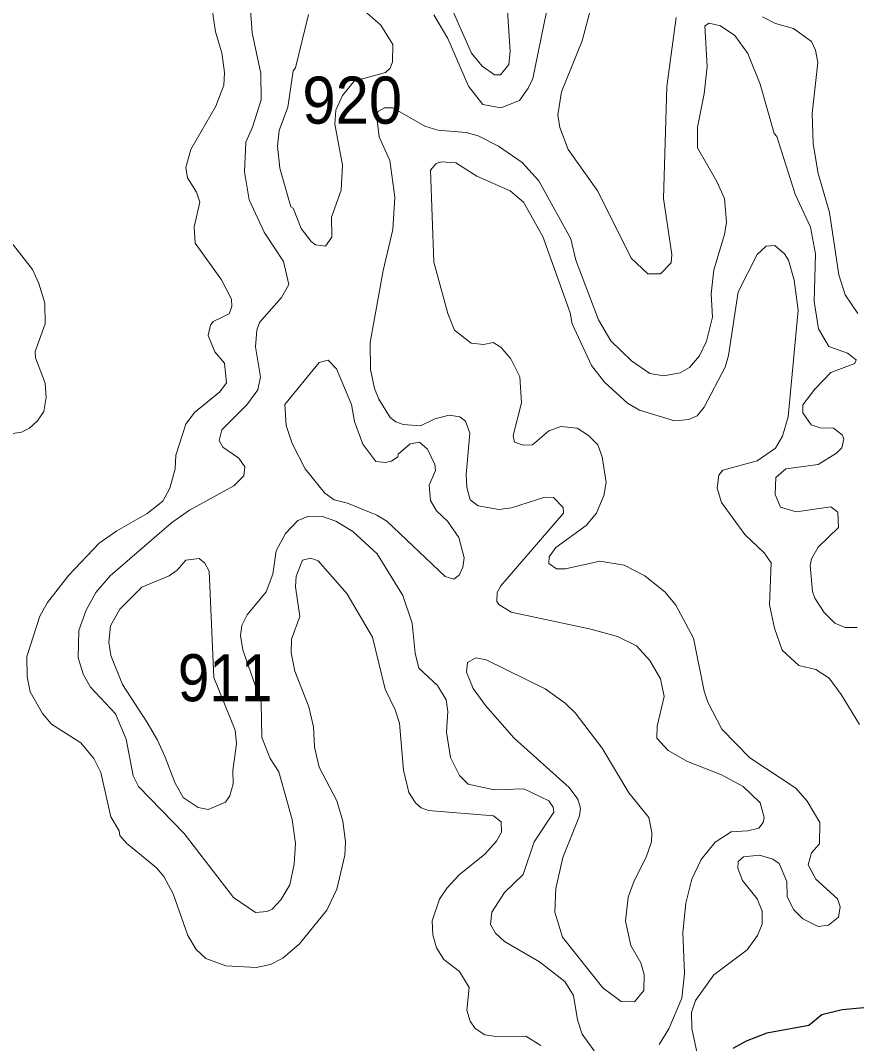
# Model space of a CAD drawing. Extents: x 763.2 to 816.8, y 7896.5 to 7952.7.
# Drawn here: x 767.387 to 770.229, y 7935.931 to 7939.409 of the extents above; entities that cross this region are included whole.
import ezdxf

# ---------------------------------------------------------------- set-up
doc = ezdxf.new("R2010")
doc.units = 0
doc.header["$LTSCALE"] = 0.064
doc.layers.add('1', color=7, linetype='Continuous', lineweight=25)
doc.layers.add('2', color=7, linetype='Continuous', lineweight=13)
doc.layers.add('21', color=7, linetype='Continuous')

msp = doc.modelspace()

# ---------------------------------------------------------------- linework, layer by layer
at = {"layer": '1'}
msp.add_lwpolyline([(770.2539, 7936.0529), (770.1802, 7936.0457), (770.1103, 7936.0282), (770.0661, 7935.9925), (769.9238, 7935.9668), (769.853, 7935.9394), (769.8084, 7935.9144)], dxfattribs=at)
at = {"layer": '2'}
for points in [[(768.8191, 7939.527), (768.9205, 7939.2984), (768.9566, 7939.254), (768.9981, 7939.2244), (769.0189, 7939.2247), (769.0465, 7939.2592), (769.0518, 7939.3042), (769.0421, 7939.4422)], [(767.551, 7937.5229), (767.655, 7937.6317), (767.7146, 7937.6738), (767.8181, 7937.7329), (767.8707, 7937.7754), (767.8943, 7937.8196), (767.9128, 7937.8844), (767.9149, 7937.9317), (767.9496, 7938.0367), (767.9782, 7938.0767), (768.0647, 7938.1468), (768.0873, 7938.1773), (768.0806, 7938.2443), (768.0482, 7938.2822), (768.025, 7938.3384), (768.0325, 7938.3732), (768.0416, 7938.3861), (768.0961, 7938.4122), (768.105, 7938.4373), (768.1048, 7938.4622), (768.07, 7938.5279), (767.9805, 7938.6517), (767.9771, 7938.7076), (767.9966, 7938.7915), (767.9854, 7938.8259), (767.9547, 7938.8737), (767.9492, 7938.9098), (767.9662, 7938.971), (768.051, 7939.1176), (768.0777, 7939.1891), (768.0806, 7939.2326), (768.0711, 7939.2991), (768.0497, 7939.37), (768.0363, 7939.4627)], [(768.1122, 7937.8272), (768.1462, 7937.8611), (768.1493, 7937.8914), (768.1288, 7937.9216), (768.0746, 7937.9585), (768.0627, 7937.9808), (768.0717, 7938.0175), (768.1562, 7938.1019), (768.1937, 7938.1539), (768.2023, 7938.198), (768.1859, 7938.2998), (768.1901, 7938.356), (768.1994, 7938.3829), (768.2745, 7938.4671), (768.2991, 7938.511), (768.2813, 7938.5895), (768.2158, 7938.6897), (768.1649, 7938.7992), (768.1485, 7938.8943), (768.1525, 7938.9959), (768.1761, 7939.0459), (768.2055, 7939.1388), (768.2039, 7939.2286), (768.1745, 7939.3666), (768.1678, 7939.4601)], [(769.3262, 7939.4555), (769.2965, 7939.3404), (769.226, 7939.1662), (769.2131, 7939.0886), (769.2206, 7939.0451), (769.2488, 7938.9703), (769.3491, 7938.8283), (769.4629, 7938.6007), (769.5195, 7938.5479), (769.5629, 7938.5475), (769.5986, 7938.585), (769.6007, 7938.6133), (769.5729, 7938.8039), (769.5841, 7939.1843), (769.6155, 7939.4193)], [(768.3664, 7939.4292), (768.3219, 7939.2487), (768.3143, 7939.2374), (768.296, 7939.1143), (768.2664, 7939.0355), (768.2609, 7938.982), (768.2685, 7938.9073), (768.3059, 7938.7756), (768.3137, 7938.7705), (768.3415, 7938.7015), (768.375, 7938.6575), (768.3901, 7938.6469), (768.4238, 7938.6415), (768.4448, 7938.6725), (768.4441, 7938.7409), (768.4768, 7938.8323), (768.4816, 7938.9176), (768.4552, 7939.0566), (768.4589, 7939.1042), (768.4817, 7939.1537), (768.5212, 7939.2028), (768.6281, 7939.2321), (768.6434, 7939.2466), (768.651, 7939.2686), (768.6526, 7939.3272), (768.6114, 7939.3936), (768.5572, 7939.4413)], [(768.7922, 7939.4282), (768.8399, 7939.3476), (768.9093, 7939.186), (768.9587, 7939.1236), (769.0199, 7939.1127), (769.083, 7939.1375), (769.113, 7939.179), (769.1284, 7939.212), (769.1747, 7939.4382)], [(769.9092, 7939.422), (769.9535, 7939.3989), (770.0139, 7939.3817), (770.0752, 7939.3377), (770.0891, 7939.3086), (770.097, 7939.2668), (770.0775, 7939.0927), (770.081, 7938.9903), (770.0983, 7938.8891), (770.1363, 7938.7567), (770.169, 7938.5446), (770.1895, 7938.476), (770.2331, 7938.413)], [(770.1647, 7937.7375), (770.1415, 7937.7551), (770.0239, 7937.7388), (769.9705, 7937.7543), (769.9524, 7937.7977), (769.9547, 7937.8557), (769.9884, 7937.8845), (770.0987, 7937.9), (770.1604, 7937.9379), (770.1782, 7937.9562), (770.1859, 7937.9868), (770.1803, 7938.0006), (770.1503, 7938.0228), (770.1045, 7938.0244), (770.0745, 7938.034), (770.0464, 7938.0757), (770.0462, 7938.1024), (770.0867, 7938.1557), (770.141, 7938.2118), (770.2232, 7938.2429), (770.2269, 7938.2552), (770.1981, 7938.2782), (770.1347, 7938.3013), (770.0991, 7938.3609), (770.0841, 7938.4536), (770.0888, 7938.6153), (770.0726, 7938.706), (770.0197, 7938.8191), (769.9575, 7939.0149), (769.9491, 7939.0251), (769.9007, 7939.1923), (769.8588, 7939.2973), (769.8148, 7939.3583), (769.7662, 7939.3905), (769.7281, 7939.4), (769.7133, 7939.3907), (769.7207, 7939.253), (769.7108, 7939.1596), (769.688, 7939.0459), (769.6885, 7938.9757), (769.7533, 7938.8618), (769.7794, 7938.8034), (769.7865, 7938.7231), (769.78, 7938.6811), (769.7437, 7938.5613), (769.734, 7938.4799), (769.7388, 7938.4005), (769.7191, 7938.3188), (769.695, 7938.2695), (769.6604, 7938.229), (769.6297, 7938.2114), (769.5736, 7938.2006), (769.5264, 7938.2092), (769.4639, 7938.2519), (769.3933, 7938.3195), (769.3511, 7938.3912), (769.275, 7938.5945), (769.2575, 7938.6665), (769.1489, 7938.8644), (769.0919, 7938.9264), (769.0118, 7938.9815), (768.9424, 7939.017), (768.9023, 7939.0287), (768.806, 7939.0366), (768.7609, 7939.0496), (768.6522, 7939.1124), (768.6241, 7939.1122), (768.6036, 7939.1008), (768.5967, 7939.0884), (768.6064, 7939.0133), (768.6426, 7938.9328), (768.6592, 7938.8083), (768.6528, 7938.6982), (768.6199, 7938.5595), (768.5754, 7938.3148), (768.5772, 7938.2229), (768.5903, 7938.1579), (768.6051, 7938.1217), (768.6439, 7938.0599), (768.6626, 7938.0444), (768.6872, 7938.0351), (768.7462, 7938.0315), (768.7959, 7938.0553), (768.844, 7938.0672), (768.8805, 7938.0615), (768.8992, 7938.0471), (768.9138, 7938.0059), (768.9024, 7937.8659), (768.9043, 7937.8211), (768.9159, 7937.7796), (768.9432, 7937.7593), (769.0132, 7937.7471), (769.0559, 7937.7525), (769.1694, 7937.788), (769.1992, 7937.7879)], [(769.9328, 7937.4222), (769.9389, 7937.5648), (769.9146, 7937.5989), (769.849, 7937.6615), (769.7699, 7937.7706), (769.7555, 7937.8186), (769.7604, 7937.8628), (769.7744, 7937.8801), (769.8904, 7937.9124), (769.9531, 7937.9546), (769.9768, 7937.9961), (769.9963, 7938.0611), (770.0297, 7938.424), (770.0166, 7938.5259), (769.997, 7938.5943), (769.9838, 7938.6158), (769.9506, 7938.644), (769.9216, 7938.6423), (769.8905, 7938.6135), (769.826, 7938.4865), (769.7929, 7938.2696), (769.7817, 7938.2308), (769.7107, 7938.0941), (769.6866, 7938.0648), (769.6583, 7938.0527), (769.6097, 7938.0477), (769.4908, 7938.084), (769.4501, 7938.1086), (769.3718, 7938.1797), (769.3274, 7938.2366), (769.2625, 7938.3774), (769.2554, 7938.4147), (769.1629, 7938.675), (769.0972, 7938.791), (769.0511, 7938.8302), (768.938, 7938.8796), (768.867, 7938.9252), (768.8176, 7938.9285), (768.8003, 7938.9233), (768.781, 7938.9006), (768.7924, 7938.5879), (768.8395, 7938.4133), (768.8624, 7938.3563), (768.9184, 7938.3121), (768.9604, 7938.3073), (768.9932, 7938.3139), (769.0194, 7938.2982), (769.0538, 7938.2591), (769.0843, 7938.1974), (769.0897, 7938.1094), (769.0621, 7937.9982), (769.0666, 7937.976), (769.0956, 7937.9658), (769.1278, 7937.967), (769.1831, 7938.0138), (769.2238, 7938.0293), (769.2786, 7938.0229), (769.3171, 7937.9978), (769.3494, 7937.9663), (769.3641, 7937.9256), (769.3772, 7937.8382), (769.3693, 7937.7939), (769.3443, 7937.7339), (769.3095, 7937.6926), (769.2071, 7937.6175), (769.1835, 7937.5858), (769.1823, 7937.5627), (769.2084, 7937.5447), (769.239, 7937.5451), (769.356, 7937.571), (769.4389, 7937.5568), (769.5091, 7937.521), (769.5777, 7937.4659), (769.6147, 7937.4217), (769.6746, 7937.3097), (769.7103, 7937.1289), (769.7231, 7937.0915), (769.7705, 7937.0003), (769.866, 7936.9019), (770.0221, 7936.7997), (770.0604, 7936.7549), (770.1039, 7936.6821), (770.1025, 7936.6102), (770.0759, 7936.5799), (770.0647, 7936.5388), (770.0904, 7936.4901), (770.1636, 7936.4231), (770.1725, 7936.3959), (770.1678, 7936.3606), (770.1337, 7936.3329), (770.0984, 7936.3287), (770.0457, 7936.3554), (770.0144, 7936.3869), (769.9923, 7936.4308), (769.9917, 7936.4822)], [(767.3266, 7938.913), (767.2924, 7938.8208), (767.292, 7938.7792), (767.3036, 7938.7324), (767.3188, 7938.7022), (767.4281, 7938.562)], [(767.4281, 7938.562), (767.4498, 7938.5154), (767.4704, 7938.4485), (767.4707, 7938.3774), (767.4366, 7938.2835), (767.4383, 7938.2623), (767.4707, 7938.1763), (767.4741, 7938.1268), (767.4663, 7938.08), (767.4454, 7938.0485), (767.4172, 7938.0235), (767.3902, 7938.0092), (767.3517, 7938.0035)], [(767.61, 7937.4038), (767.6436, 7937.4642), (767.6923, 7937.5212), (767.8999, 7937.7008), (767.9618, 7937.7448), (768.1122, 7937.8272)], [(769.1992, 7937.7879), (769.2317, 7937.7532), (769.2325, 7937.7337), (769.0201, 7937.4868), (769.0073, 7937.4647), (769.0064, 7937.4337)], [(769.3369, 7935.9058), (769.2966, 7935.9628), (769.2803, 7936.0121), (769.2668, 7936.0942), (769.2369, 7936.1418), (769.1515, 7936.209), (769.0321, 7936.2777), (769.0019, 7936.3061), (768.9848, 7936.336), (768.9889, 7936.3776), (769.0316, 7936.4447), (769.0953, 7936.5059), (769.1327, 7936.6168), (769.1994, 7936.7175), (769.1979, 7936.7343), (769.1832, 7936.7556), (769.0976, 7936.7965), (768.9971, 7936.7938), (768.9084, 7936.8131), (768.879, 7936.842), (768.8484, 7936.903), (768.8349, 7936.9898), (768.8398, 7937.0599), (768.8335, 7937.0999), (768.8041, 7937.1481), (768.7413, 7937.2071), (768.7285, 7937.2581), (768.7179, 7937.3598), (768.6863, 7937.4539), (768.5999, 7937.5957), (768.5171, 7937.6717), (768.4588, 7937.7065), (768.4138, 7937.7227), (768.3667, 7937.7238), (768.3296, 7937.7089), (768.2877, 7937.6647), (768.2565, 7937.6056), (768.2446, 7937.5263), (768.2222, 7937.4667), (768.1579, 7937.3886), (768.1397, 7937.3519), (768.135, 7937.3183), (768.1425, 7937.269), (768.2053, 7937.0903), (768.2072, 7936.9713), (768.2362, 7936.8998), (768.2647, 7936.8552), (768.3104, 7936.6924), (768.3221, 7936.611), (768.3172, 7936.5413), (768.3021, 7936.471), (768.2722, 7936.4197), (768.2422, 7936.3883), (768.2252, 7936.3796), (768.1853, 7936.3767), (768.1114, 7936.4278), (767.943, 7936.6453), (767.7884, 7936.8044), (767.7696, 7936.8412), (767.746, 7936.9653), (767.71, 7937.0514), (767.6254, 7937.1422), (767.6011, 7937.1842), (767.583, 7937.2426), (767.5859, 7937.3354), (767.61, 7937.4038)], [(770.0789, 7937.4682), (770.071, 7937.5564), (770.076, 7937.5791), (770.098, 7937.6181), (770.1676, 7937.6857), (770.1647, 7937.7375)], [(769.1554, 7935.9243), (769.1045, 7935.9556), (769.0109, 7935.954), (768.9651, 7935.9607), (768.9322, 7935.9823), (768.9158, 7936.0068), (768.904, 7936.045), (768.9124, 7936.122), (768.8791, 7936.176), (768.826, 7936.2163), (768.8006, 7936.2565), (768.7891, 7936.3001), (768.7864, 7936.3483), (768.8117, 7936.4217), (768.8373, 7936.4605), (768.8777, 7936.5045), (768.9648, 7936.5752), (769.0053, 7936.619), (769.0221, 7936.6492), (769.0206, 7936.6845), (768.9945, 7936.705), (768.7741, 7936.7231), (768.7488, 7936.7327), (768.7293, 7936.7498), (768.7069, 7936.7846), (768.6885, 7936.8609), (768.6757, 7937.0198), (768.661, 7937.0659), (768.6267, 7937.136), (768.5834, 7937.313), (768.4963, 7937.4609), (768.3992, 7937.5716), (768.3737, 7937.581), (768.3458, 7937.5744), (768.3238, 7937.5203), (768.3223, 7937.4842), (768.337, 7937.3833), (768.3081, 7937.3056), (768.3075, 7937.2588), (768.3192, 7937.1974), (768.3667, 7937.0757), (768.3828, 7937.0081), (768.3864, 7936.939), (768.4024, 7936.8708), (768.4628, 7936.7557), (768.4828, 7936.6867), (768.4914, 7936.6162), (768.4899, 7936.5717), (768.4621, 7936.4559), (768.4281, 7936.3848), (768.3358, 7936.2701), (768.2783, 7936.2207), (768.2365, 7936.1996), (768.1884, 7936.189), (768.0846, 7936.1955), (768.0172, 7936.2206), (767.9842, 7936.2509), (767.9555, 7936.2981), (767.9062, 7936.4394), (767.8748, 7936.4985), (767.849, 7936.5287), (767.7475, 7936.6126), (767.7247, 7936.6387), (767.722, 7936.6537), (767.6942, 7936.7014), (767.6601, 7936.8523), (767.6361, 7936.9003), (767.5924, 7936.9531), (767.493, 7937.0167), (767.4618, 7937.0531), (767.4196, 7937.1272)], [(767.4196, 7937.1272), (767.4093, 7937.1772), (767.4085, 7937.2473), (767.4524, 7937.384), (767.4788, 7937.4308), (767.551, 7937.5229)], [(770.2307, 7937.345), (770.1905, 7937.3458), (770.1545, 7937.3598), (770.119, 7937.3964), (770.0873, 7937.4446), (770.0789, 7937.4682)], [(769.0064, 7937.4337), (769.0124, 7937.4238), (769.0543, 7937.397), (769.3256, 7937.3395), (769.4157, 7937.3143)], [(770.1354, 7937.1727), (770.0903, 7937.2029), (770.0328, 7937.2165), (769.9754, 7937.2678), (769.9494, 7937.3427), (769.9328, 7937.4222)], [(769.4157, 7937.3143), (769.4807, 7937.2834), (769.5262, 7937.2328), (769.5619, 7937.1704), (769.5744, 7937.1111), (769.5515, 7937.01), (769.5498, 7936.9696), (769.5882, 7936.9272), (769.6545, 7936.8894), (769.7695, 7936.8449), (769.843, 7936.8048), (769.9007, 7936.7489), (769.9146, 7936.6991), (769.9112, 7936.6822), (769.8967, 7936.6634), (769.8588, 7936.6541), (769.8029, 7936.6505), (769.7484, 7936.6153), (769.701, 7936.557), (769.6694, 7936.49), (769.6485, 7936.4085), (769.6387, 7936.3088), (769.6435, 7936.1692), (769.6348, 7936.0857), (769.5905, 7935.9813), (769.5573, 7935.9272)], [(770.2385, 7937.0152), (770.1768, 7937.1171), (770.1354, 7937.1727)], [(769.9917, 7936.4822), (769.9659, 7936.5431), (769.9445, 7936.5576), (769.8983, 7936.5717), (769.8442, 7936.5655), (769.8261, 7936.5495)], [(769.8261, 7936.5495), (769.8247, 7936.5271), (769.8406, 7936.4855), (769.8912, 7936.4229), (769.9083, 7936.3805), (769.9081, 7936.3368), (769.8919, 7936.2979), (769.857, 7936.2498), (769.7439, 7936.1642), (769.6814, 7936.0772), (769.6682, 7936.037), (769.669, 7935.9822), (769.7056, 7935.8124)]]:
    msp.add_lwpolyline(points, dxfattribs=at)
for points in [[(768.6317, 7937.7066), (768.5986, 7937.7278), (768.4987, 7937.768), (768.4535, 7937.7794), (768.4214, 7937.8021), (768.3545, 7937.8849), (768.3108, 7937.9705), (768.2905, 7938.0319), (768.2859, 7938.1032), (768.4021, 7938.2459), (768.4326, 7938.2543), (768.4611, 7938.2248), (768.5116, 7938.1038), (768.5228, 7938.0461), (768.5502, 7937.9685), (768.5953, 7937.9101), (768.627, 7937.9063), (768.6486, 7937.9111), (768.6698, 7937.9255), (768.6712, 7937.9346), (768.7112, 7937.9703), (768.7432, 7937.9753), (768.7706, 7937.9521), (768.7949, 7937.8996), (768.7972, 7937.879), (768.776, 7937.8291), (768.7808, 7937.7767), (768.8009, 7937.7423), (768.8382, 7937.7071), (768.877, 7937.6513), (768.8955, 7937.5826), (768.8909, 7937.5504), (768.8775, 7937.5236), (768.8599, 7937.5103), (768.83, 7937.5186)], [(768.1101, 7936.8141), (768.1086, 7936.8594), (768.1216, 7936.95), (768.1168, 7936.996), (768.0444, 7937.1757), (768.028, 7937.5372), (768.0142, 7937.5647), (767.9941, 7937.5803), (767.9487, 7937.5738), (767.9199, 7937.5403), (767.892, 7937.5211), (767.7997, 7937.4822), (767.7252, 7937.4077), (767.693, 7937.3507), (767.6878, 7937.2956), (767.6947, 7937.25), (767.7342, 7937.1514), (767.8174, 7937.0223), (767.8529, 7936.9628), (767.8783, 7936.9043), (767.9115, 7936.819), (767.9395, 7936.7675), (767.9907, 7936.7337), (768.0247, 7936.7265), (768.0841, 7936.7516), (768.0987, 7936.773)], [(769.4429, 7936.3471), (769.4523, 7936.429), (769.4724, 7936.4841), (769.5139, 7936.5643), (769.5318, 7936.6169), (769.5334, 7936.6485), (769.5226, 7936.6996), (769.4551, 7936.7833), (769.3637, 7936.9356), (769.272, 7937.0548), (769.2387, 7937.0883), (769.1701, 7937.1371), (768.9694, 7937.2352), (768.9348, 7937.2423), (768.9069, 7937.2262), (768.9026, 7937.1932), (768.9252, 7937.1377), (768.9675, 7937.0805), (769.0648, 7936.9697), (769.2514, 7936.8013), (769.281, 7936.762), (769.29, 7936.7313), (769.2871, 7936.7046), (769.2304, 7936.5637), (769.2064, 7936.4584), (769.203, 7936.3777), (769.2287, 7936.2929), (769.3669, 7936.1204), (769.4282, 7936.0741), (769.4744, 7936.0729), (769.506, 7936.111), (769.5071, 7936.1659), (769.4955, 7936.2054), (769.4614, 7936.2639)]]:
    msp.add_lwpolyline(points, close=True, dxfattribs=at)

# ---------------------------------------------------------------- texts
at = {"layer": '21'}
for s, width, p in [('920', 0.95, (768.345, 7939.0583)), ('911', 0.9, (767.9219, 7937.0947))]:
    msp.add_text(s, height=0.16, dxfattribs=dict(at, width=width)).set_placement(p)

doc.saveas('drawing.dxf')
